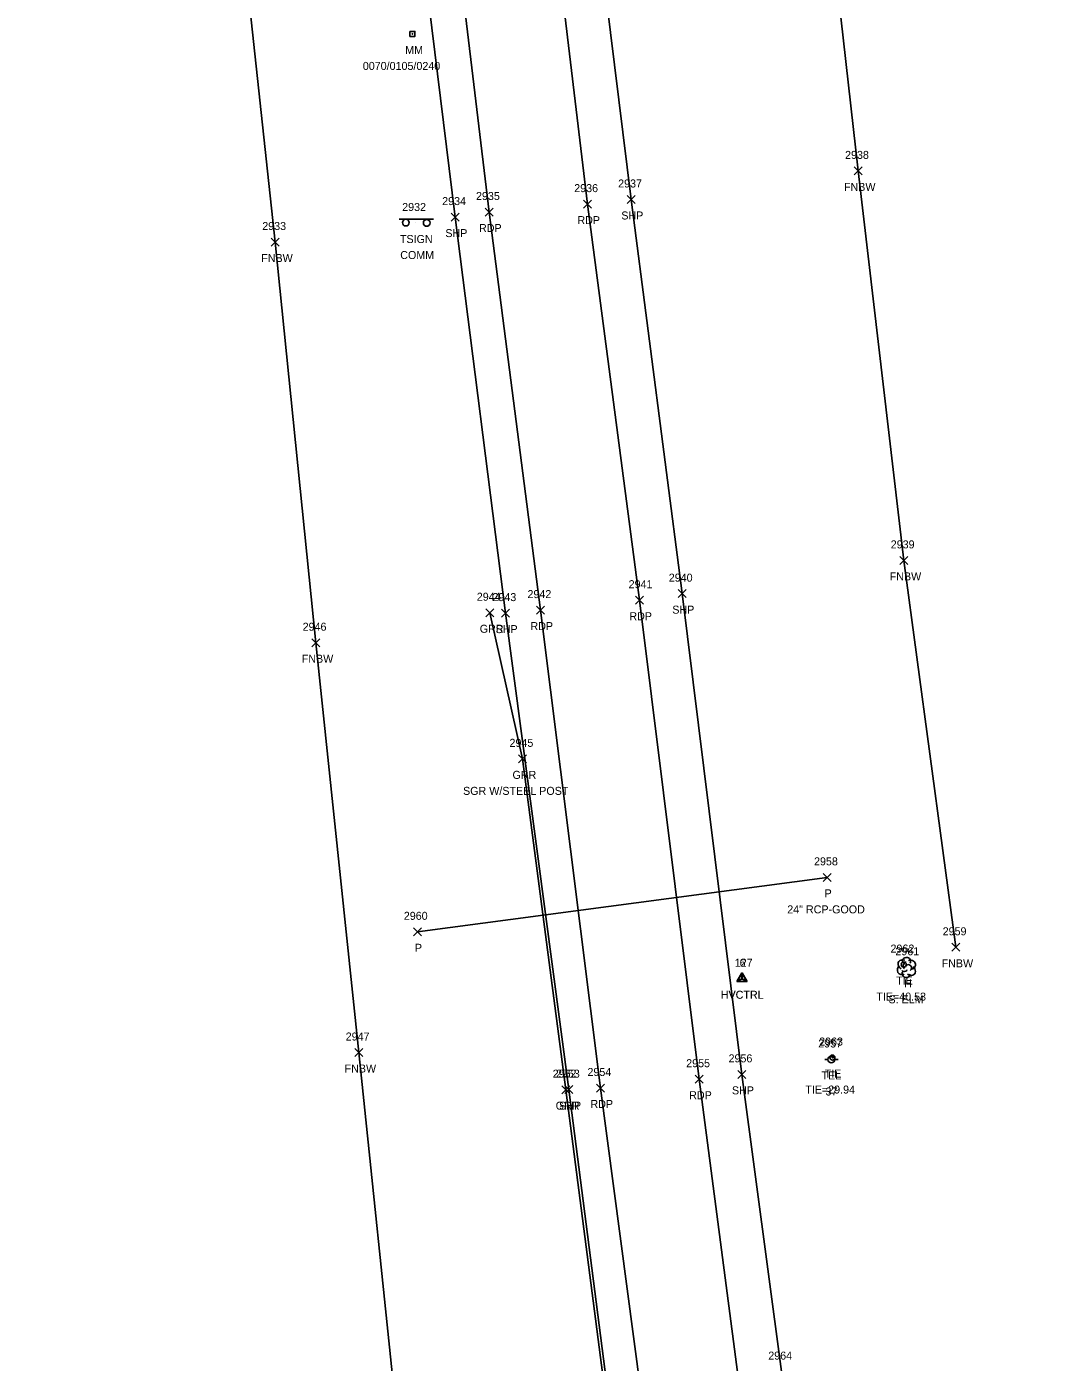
# Model space of a CAD drawing. Extents: x 1443071 to 1445292, y 614024 to 622563.
# Drawn here: x 1443966.2 to 1444221.3, y 618552.3 to 618886.1 of the extents above; entities that cross this region are included whole.
import ezdxf

# ---------------------------------------------------------------- set-up
doc = ezdxf.new("R2010")
doc.units = 0
for name, color, linetype in [('C_A', 7, 'Continuous'), ('C_C', 7, 'Continuous'), ('C_I', 7, 'Continuous'), ('CBP', 7, 'Continuous'), ('CPSM', 7, 'Continuous'), ('D_A', 7, 'Continuous'), ('D_C', 7, 'Continuous'), ('D_I', 7, 'Continuous'), ('D_TIC', 7, 'Continuous'), ('DCP', 7, 'Continuous'), ('L_A', 7, 'Continuous'), ('L_C', 7, 'Continuous'), ('L_I', 7, 'Continuous'), ('L_TIC', 7, 'Continuous'), ('LFNC', 7, 'Continuous'), ('LTD', 7, 'Continuous'), ('P_A', 7, 'Continuous'), ('P_I', 7, 'Continuous'), ('P_TIC', 7, 'Continuous'), ('PET', 7, 'Continuous'), ('PSP', 7, 'Continuous'), ('R_A', 7, 'Continuous'), ('R_C', 7, 'Continuous'), ('R_I', 7, 'Continuous'), ('R_TIC', 7, 'Continuous'), ('RGR', 7, 'Continuous'), ('S_A', 7, 'Continuous'), ('S_C', 7, 'Continuous'), ('S_I', 7, 'Continuous'), ('SRM', 7, 'Continuous'), ('SSGN', 7, 'Continuous'), ('U_A', 7, 'Continuous'), ('U_C', 7, 'Continuous'), ('U_I', 7, 'Continuous'), ('UP', 7, 'Continuous')]:
    doc.layers.add(name, color=color, linetype=linetype)

msp = doc.modelspace()

# ---------------------------------------------------------------- linework, layer by layer
at = {"layer": 'CBP'}
for centre, radius in [((1444185.23, 618651.69), 0.625), ((1444185.23, 618651.69), 0.0833), ((1444167.41, 618628.46), 0.625), ((1444167.41, 618628.46), 0.0833)]:
    msp.add_circle(centre, radius, dxfattribs=at)
at = {"layer": 'CPSM'}
for p, q in [((1444143.57, 618647.44), (1444144.82, 618649.6)), ((1444143.57, 618647.44), (1444144.82, 618648.16)), ((1444143.57, 618647.44), (1444146.07, 618647.44)), ((1444143.61, 618647.43), (1444144.86, 618649.6)), ((1444143.61, 618647.43), (1444144.86, 618648.15)), ((1444143.61, 618647.43), (1444146.11, 618647.43)), ((1444146.07, 618647.44), (1444144.82, 618649.6)), ((1444144.82, 618648.16), (1444144.82, 618649.6)), ((1444144.82, 618648.16), (1444144.82, 618648.16)), ((1444144.82, 618648.16), (1444146.07, 618647.44)), ((1444146.11, 618647.43), (1444144.86, 618649.6)), ((1444144.86, 618648.15), (1444144.86, 618649.6)), ((1444144.86, 618648.15), (1444144.86, 618648.15)), ((1444144.86, 618648.15), (1444146.11, 618647.43))]:
    msp.add_line(p, q, dxfattribs=at)
at = {"layer": 'D_TIC'}
for points in [[(1444165.08, 618672.49), (1444167.08, 618674.49)], [(1444167.08, 618672.49), (1444165.08, 618674.49)], [(1444062.76, 618658.88), (1444064.76, 618660.88)], [(1444064.76, 618658.88), (1444062.76, 618660.88)]]:
    msp.add_lwpolyline(points, dxfattribs=at)
at = {"layer": 'DCP'}
msp.add_lwpolyline([(1444166.08, 618673.49), (1444063.76, 618659.88)], dxfattribs=at)
at = {"layer": 'L_TIC'}
for points in [[(1444172.83, 618849.02), (1444174.83, 618851.02)], [(1444174.83, 618849.02), (1444172.83, 618851.02)], [(1444027.26, 618831.25), (1444029.26, 618833.25)], [(1444029.26, 618831.25), (1444027.26, 618833.25)], [(1444184.25, 618751.69), (1444186.25, 618753.69)], [(1444186.25, 618751.69), (1444184.25, 618753.69)], [(1444037.4, 618731.12), (1444039.4, 618733.12)], [(1444039.4, 618731.12), (1444037.4, 618733.12)], [(1444197.22, 618655.01), (1444199.22, 618657.01)], [(1444199.22, 618655.01), (1444197.22, 618657.01)], [(1444048.1, 618628.72), (1444050.1, 618630.72)], [(1444050.1, 618628.72), (1444048.1, 618630.72)]]:
    msp.add_lwpolyline(points, dxfattribs=at)
at = {"layer": 'LFNC'}
for points in [[(1444140.95, 619617.62), (1444141.66, 619543.48), (1444143.47, 619453.28), (1444144.69, 619378.28), (1444145.89, 619275.11), (1444147.59, 619182.81), (1444151.11, 619052.76), (1444160.95, 618964.58), (1444173.83, 618850.02), (1444185.25, 618752.69), (1444198.22, 618656.01)], [(1443966.17, 618998.47), (1444007.8, 619005.6), (1444017.48, 618931.86), (1444028.26, 618832.25), (1444038.4, 618732.12), (1444049.1, 618629.72), (1444058.56, 618539.25), (1444065.36, 618471.37), (1444074.33, 618387.05), (1444083.93, 618296.19)]]:
    msp.add_lwpolyline(points, dxfattribs=at)
at = {"layer": 'LTD'}
msp.add_line((1444185.87, 618651.02), (1444185.87, 618651.02), dxfattribs=at)
msp.add_line((1444185.87, 618651.02), (1444185.87, 618651.02), dxfattribs=at)
msp.add_arc((1444185.91, 618652.45), 1.05, 335.5272, 180.9563, dxfattribs=at)
for centre, major_axis, ratio, start_param, end_param in [((1444184.78, 618650.31), (0.58, -1.04), 0.959034, 3.141593, 6.283185), ((1444185.08, 618651.69), (1.21, -0.51), 0.895232, 1.570796, 4.712389), ((1444185.66, 618651.48), (-0.208, -0.792), 0.645439, 3.141593, 6.283185), ((1444186.37, 618650.85), (-0.5, 0.667), 0.989748, 3.141593, 6.283185), ((1444186.87, 618650.19), (-1.09, 0.79), 0.841452, 1.570796, 4.712389), ((1444186.91, 618651.6), (-1.14, -0.48), 0.949671, 1.570796, 4.712389), ((1444185.87, 618649.52), (0.26, 1.06), 0.942809, 1.570796, 4.712389), ((1444185.41, 618650.27), (-0.625, -0.083), 0.423636, 0, 3.141593)]:
    msp.add_ellipse(centre, major_axis=major_axis, ratio=ratio, start_param=start_param, end_param=end_param, dxfattribs=at)
at = {"layer": 'P_TIC'}
for points in [[(1444105.23, 618840.72), (1444107.23, 618842.72)], [(1444107.23, 618840.72), (1444105.23, 618842.72)], [(1444116.15, 618841.88), (1444118.15, 618843.88)], [(1444118.15, 618841.88), (1444116.15, 618843.88)], [(1444072.2, 618837.48), (1444074.2, 618839.48)], [(1444074.2, 618837.48), (1444072.2, 618839.48)], [(1444080.65, 618838.75), (1444082.65, 618840.75)], [(1444082.65, 618838.75), (1444080.65, 618840.75)], [(1444128.88, 618743.38), (1444130.88, 618745.38)], [(1444130.88, 618743.38), (1444128.88, 618745.38)], [(1444093.51, 618739.27), (1444095.51, 618741.27)], [(1444095.51, 618739.27), (1444093.51, 618741.27)], [(1444118.2, 618741.75), (1444120.2, 618743.75)], [(1444120.2, 618741.75), (1444118.2, 618743.75)], [(1444084.76, 618738.52), (1444086.76, 618740.52)], [(1444086.76, 618738.52), (1444084.76, 618740.52)], [(1444133.15, 618622.05), (1444135.15, 618624.05)], [(1444135.15, 618622.05), (1444133.15, 618624.05)], [(1444143.78, 618623.26), (1444145.78, 618625.26)], [(1444145.78, 618623.26), (1444143.78, 618625.26)], [(1444100.61, 618619.44), (1444102.61, 618621.44)], [(1444102.61, 618619.44), (1444100.61, 618621.44)], [(1444108.49, 618619.85), (1444110.49, 618621.85)], [(1444110.49, 618619.85), (1444108.49, 618621.85)]]:
    msp.add_lwpolyline(points, dxfattribs=at)
at = {"layer": 'PET'}
for points in [[(1444060.23, 619757.24), (1444030.6, 619759.6), (1444027.22, 619690.19), (1444024.14, 619595.2), (1444026, 619550.02), (1444025.36, 619470.06), (1444027.67, 619387.44), (1444035.05, 619262.29), (1444046.36, 619146.08), (1444057.76, 619040.09), (1444068.86, 618946.58), (1444081.65, 618839.75), (1444094.51, 618740.27), (1444109.49, 618620.85), (1444119.47, 618545.62)], [(1444060.23, 619757.24), (1444055.7, 619686.84), (1444052.09, 619593.54), (1444051.88, 619548.79), (1444051.53, 619469.84), (1444057.39, 619386.89), (1444060.43, 619264.84), (1444070.47, 619153.76), (1444082.27, 619042.98), (1444093.27, 618950.3), (1444106.23, 618841.72), (1444119.2, 618742.75), (1444134.15, 618623.05), (1444144.16, 618546.64)]]:
    msp.add_lwpolyline(points, dxfattribs=at)
at = {"layer": 'PSP'}
for points in [[(1444030.6, 619759.6), (1444029.33, 619753.09), (1444025.71, 619690.24), (1444018.62, 619596.21), (1444016.49, 619550.78), (1444015.83, 619506.94), (1444016.35, 619478.84), (1444019.52, 619385.97), (1444025.45, 619273.62), (1444031.18, 619208.3), (1444036.73, 619143.63), (1444046.33, 619051.58), (1444050.41, 619020.07), (1444060.07, 618945.31), (1444073.2, 618838.48), (1444085.76, 618739.52), (1444101.61, 618620.44), (1444111.35, 618544.8)], [(1444060.23, 619757.24), (1444060.46, 619750.33), (1444058.96, 619686.98), (1444059.06, 619593.34), (1444060.01, 619548.92), (1444060.2, 619469.56), (1444062.86, 619388.02), (1444070.04, 619265.9), (1444080.12, 619155.61), (1444092.23, 619044.26), (1444103.72, 618951.36), (1444117.15, 618842.88), (1444129.88, 618744.38), (1444144.78, 618624.26), (1444154.69, 618549.98)]]:
    msp.add_lwpolyline(points, dxfattribs=at)
at = {"layer": 'R_TIC'}
for points in [[(1444080.85, 618738.61), (1444082.85, 618740.61)], [(1444082.85, 618738.61), (1444080.85, 618740.61)], [(1444089.02, 618702.1), (1444091.02, 618704.1)], [(1444091.02, 618702.1), (1444089.02, 618704.1)], [(1444099.8, 618619.43), (1444101.8, 618621.43)], [(1444101.8, 618619.43), (1444099.8, 618621.43)]]:
    msp.add_lwpolyline(points, dxfattribs=at)
at = {"layer": 'RGR'}
msp.add_lwpolyline([(1444081.85, 618739.61), (1444090.02, 618703.1), (1444100.8, 618620.43), (1444110.62, 618544.53), (1444122.19, 618455.29), (1444135.7, 618350.74), (1444148.14, 618256.46), (1444159.76, 618166.72), (1444169.23, 618095.42), (1444182.66, 617992.67), (1444194.01, 617906.07), (1444204.2, 617827.38), (1444217.72, 617718.99), (1444221.33, 617660.88)], dxfattribs=at)
at = {"layer": 'SRM'}
msp.add_lwpolyline([(1444061.88, 618884.88), (1444063.13, 618884.88), (1444063.13, 618883.63), (1444061.88, 618883.63)], close=True, dxfattribs=at)
msp.add_circle((1444062.51, 618884.25), 0.0833, dxfattribs=at)
at = {"layer": 'SSGN'}
for p, q in [((1444059.19, 618837.93), (1444067.79, 618837.93)), ((1444063.21, 618837.02), (1444063.21, 618837.02))]:
    msp.add_line(p, q, dxfattribs=at)
for centre in [(1444060.85, 618837.09), (1444066.07, 618837.02)]:
    msp.add_circle(centre, 0.833, dxfattribs=at)
at = {"layer": 'UP'}
for p, q in [((1444165.49, 618627.98), (1444166.31, 618627.98)), ((1444167.14, 618627.98), (1444167.14, 618627.98)), ((1444168.81, 618627.98), (1444167.98, 618627.98)), ((1444167.98, 618627.98), (1444167.98, 618627.98)), ((1444168.81, 618627.98), (1444168.81, 618627.98))]:
    msp.add_line(p, q, dxfattribs=at)
msp.add_circle((1444167.14, 618627.98), 0.833, dxfattribs=at)

# ---------------------------------------------------------------- texts
at = {"layer": 'C_A'}
for s, p in [('TIE', (1444183.31, 618646.69)), ('HVCTRL', (1444139.51, 618643.16)), ('HVCTRL', (1444139.55, 618643.15)), ('TIE', (1444165.49, 618623.46))]:
    msp.add_text(s, height=2, dxfattribs=at).set_placement(p)
at = {"layer": 'C_C'}
for s, p in [('TIE=40.53', (1444178.38, 618642.69)), ('TIE=29.94', (1444160.64, 618619.46))]:
    msp.add_text(s, height=2, dxfattribs=at).set_placement(p)
at = {"layer": 'C_I'}
for s, p in [('2962', (1444181.92, 618654.69)), ('127', (1444143.02, 618651.16)), ('6', (1444144.23, 618651.15)), ('2963', (1444164.1, 618631.46))]:
    msp.add_text(s, height=2, dxfattribs=at).set_placement(p)
at = {"layer": 'D_A'}
for p in [(1444165.46, 618668.49), (1444063.14, 618654.88)]:
    msp.add_text('P', height=2, dxfattribs=at).set_placement(p)
at = {"layer": 'D_C'}
msp.add_text('24" RCP-GOOD', height=2, dxfattribs=at).set_placement((1444156.13, 618664.49))
at = {"layer": 'D_I'}
for s, p in [('2958', (1444162.82, 618676.49)), ('2960', (1444060.36, 618662.88))]:
    msp.add_text(s, height=2, dxfattribs=at).set_placement(p)
at = {"layer": 'L_A'}
for s, p in [('FNBW', (1444170.3, 618845.02)), ('FNBW', (1444024.74, 618827.25)), ('FNBW', (1444181.72, 618747.69)), ('FNBW', (1444034.87, 618727.12)), ('FNBW', (1444194.69, 618651.01)), ('H', (1444185.3, 618646.02)), ('FNBW', (1444045.57, 618624.72))]:
    msp.add_text(s, height=2, dxfattribs=at).set_placement(p)
at = {"layer": 'L_C'}
msp.add_text('S. ELM', height=2, dxfattribs=at).set_placement((1444181.41, 618642.02))
at = {"layer": 'L_I'}
for s, p in [('2938', (1444170.57, 618853.02)), ('2933', (1444025, 618835.25)), ('2939', (1444181.98, 618755.69)), ('2946', (1444035.09, 618735.12)), ('2959', (1444194.95, 618659.01)), ('2961', (1444183.13, 618654.02)), ('2947', (1444045.84, 618632.72))]:
    msp.add_text(s, height=2, dxfattribs=at).set_placement(p)
at = {"layer": 'P_A'}
for s, p in [('RDP', (1444103.72, 618836.72)), ('SHP', (1444114.68, 618837.88)), ('SHP', (1444070.73, 618833.48)), ('RDP', (1444079.14, 618834.75)), ('SHP', (1444127.42, 618739.38)), ('RDP', (1444116.69, 618737.75)), ('SHP', (1444083.29, 618734.52)), ('RDP', (1444091.99, 618735.27)), ('SHP', (1444142.32, 618619.26)), ('SHP', (1444099.15, 618615.44)), ('RDP', (1444106.98, 618615.85)), ('RDP', (1444131.64, 618618.05))]:
    msp.add_text(s, height=2, dxfattribs=at).set_placement(p)
at = {"layer": 'P_I'}
for s, p in [('2937', (1444113.89, 618845.88)), ('2935', (1444078.39, 618842.75)), ('2936', (1444102.92, 618844.72)), ('2934', (1444069.94, 618841.48)), ('2941', (1444116.51, 618745.75)), ('2940', (1444126.54, 618747.38)), ('2943', (1444082.5, 618742.52)), ('2942', (1444091.25, 618743.27)), ('2955', (1444130.89, 618626.05)), ('2956', (1444141.47, 618627.26)), ('2953', (1444098.35, 618623.44)), ('2954', (1444106.23, 618623.85)), ('2964', (1444151.39, 618552.98))]:
    msp.add_text(s, height=2, dxfattribs=at).set_placement(p)
at = {"layer": 'R_A'}
for p in [(1444079.33, 618734.61), (1444087.51, 618698.1), (1444098.29, 618615.43)]:
    msp.add_text('GRR', height=2, dxfattribs=at).set_placement(p)
at = {"layer": 'R_C'}
msp.add_text('SGR W/STEEL POST', height=2, dxfattribs=at).set_placement((1444075.16, 618694.1))
at = {"layer": 'R_I'}
for s, p in [('2944', (1444078.59, 618742.61)), ('2945', (1444086.76, 618706.1)), ('2952', (1444097.54, 618623.43))]:
    msp.add_text(s, height=2, dxfattribs=at).set_placement(p)
at = {"layer": 'S_A'}
for s, p in [('MM', (1444060.7, 618879.25)), ('TSIGN', (1444059.39, 618832))]:
    msp.add_text(s, height=2, dxfattribs=at).set_placement(p)
at = {"layer": 'S_C'}
for s, p in [('0070/0105/0240', (1444050.12, 618875.25)), ('COMM', (1444059.47, 618828))]:
    msp.add_text(s, height=2, dxfattribs=at).set_placement(p)
at = {"layer": 'S_I'}
msp.add_text('2932', height=2, dxfattribs=at).set_placement((1444059.95, 618840))
at = {"layer": 'U_A'}
msp.add_text('TEL', height=2, dxfattribs=at).set_placement((1444164.7, 618622.98))
at = {"layer": 'U_C'}
msp.add_text('37', height=2, dxfattribs=at).set_placement((1444165.68, 618618.98))
at = {"layer": 'U_I'}
msp.add_text('2957', height=2, dxfattribs=at).set_placement((1444163.88, 618630.98))

doc.saveas('drawing.dxf')
